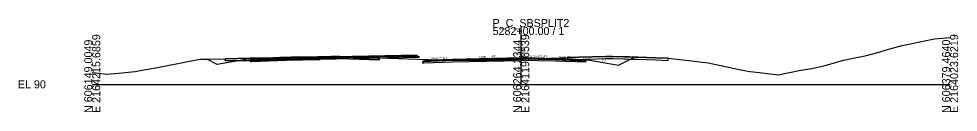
# Model space of a CAD drawing. Extents: x -26 to 1303, y -10 to 12033.
# Drawn here: x -25.7 to 302.8, y 1490.3 to 1522.8 of the extents above; entities that cross this region are included whole.
import ezdxf

# ---------------------------------------------------------------- set-up
doc = ezdxf.new("R2010")
doc.units = 0
for name, color, linetype in [('RD_GPK_XS_Cell', 7, 'Continuous'), ('RD_XS_Base', 7, 'Continuous'), ('RD_XS_ExGround', 7, 'Continuous'), ('RD_XS_ExPaveRet', 7, 'Continuous'), ('RD_XS_Greenside', 7, 'Continuous'), ('RD_XS_Pave', 7, 'Continuous'), ('RD_XS_PaveOvlay_CP', 7, 'Continuous'), ('RD_XS_TieSlope', 7, 'Continuous'), ('RD_XS_TX_Elev_EX', 7, 'Continuous'), ('RD_XS_TX_Elev_PR', 7, 'Continuous'), ('RD_XS_TX_ShdSlope', 7, 'Continuous'), ('RD_XS_TX_Slope', 7, 'Continuous')]:
    doc.layers.add(name, color=color, linetype=linetype)

msp = doc.modelspace()

# ---------------------------------------------------------------- linework, layer by layer
at = {"layer": 'RD_GPK_XS_Cell'}
for p, q in [((150, 1500), (150, 1520)), ((0, 1500), (150, 1500)), ((150, 1500), (300, 1500))]:
    msp.add_line(p, q, dxfattribs=at)
at = {"layer": 'RD_XS_Base'}
for p, q in [((55.67, 1508.47), (55.17, 1508.45)), ((55.17, 1508.45), (55.17, 1508.45)), ((55.17, 1508.45), (55.17, 1507.95)), ((55.17, 1507.95), (55.67, 1507.97)), ((67.67, 1508.95), (55.67, 1508.47)), ((55.67, 1508.47), (55.67, 1508.47)), ((55.67, 1507.97), (67.67, 1508.45)), ((55.67, 1507.97), (55.67, 1507.97)), ((79.67, 1509.19), (67.67, 1508.95)), ((67.67, 1508.95), (67.67, 1508.95)), ((67.67, 1508.45), (79.67, 1508.69)), ((67.67, 1508.45), (67.67, 1508.45)), ((79.67, 1509.19), (113.67, 1509.87)), ((114.17, 1509.38), (79.67, 1508.69)), ((79.67, 1508.69), (79.67, 1509.35)), ((79.67, 1509.35), (79.67, 1509.35)), ((79.67, 1509.35), (79.67, 1509.35)), ((79.67, 1509.35), (79.67, 1509.19)), ((79.67, 1509.19), (79.67, 1509.19)), ((79.67, 1508.69), (79.67, 1509.19)), ((79.67, 1509.19), (79.67, 1509.19)), ((79.67, 1509.19), (79.67, 1509.19)), ((79.67, 1508.69), (79.67, 1508.69)), ((103.67, 1509.67), (103.67, 1509.67)), ((103.67, 1509.67), (103.67, 1509.67)), ((103.67, 1509.17), (103.67, 1509.17)), ((103.67, 1509.17), (103.67, 1509.17)), ((113.67, 1509.87), (113.67, 1509.87)), ((114.17, 1509.88), (114.17, 1509.38)), ((114.17, 1509.85), (114.17, 1509.85)), ((116, 1507.99), (115.5, 1507.97)), ((115.5, 1507.97), (115.5, 1507.97)), ((115.5, 1507.97), (115.5, 1507.47)), ((126, 1508.39), (116, 1507.99)), ((116, 1507.99), (116, 1507.99)), ((150, 1508.87), (126, 1508.39)), ((126, 1508.39), (126, 1508.39)), ((126, 1507.89), (150, 1508.37)), ((150, 1508.37), (150, 1509.03)), ((150, 1509.03), (150, 1509.03)), ((150, 1509.03), (150, 1509.03)), ((150, 1509.03), (150, 1508.87)), ((150, 1508.87), (150, 1508.87)), ((150, 1508.87), (162, 1508.63)), ((150, 1508.87), (150, 1508.87)), ((150, 1508.37), (150, 1508.87)), ((150, 1508.87), (150, 1508.87)), ((150, 1508.87), (150, 1508.87)), ((162, 1508.13), (150, 1508.37)), ((150, 1508.37), (150, 1508.37)), ((150, 1508.37), (150, 1508.37)), ((162, 1508.63), (162, 1508.63)), ((162, 1508.63), (172, 1508.23)), ((172.5, 1507.71), (162, 1508.13)), ((162, 1508.13), (162, 1508.13)), ((172, 1508.23), (172, 1508.23)), ((172, 1508.23), (172.5, 1508.21)), ((172.5, 1508.21), (172.5, 1508.21)), ((172.5, 1508.21), (172.5, 1507.71)), ((115.5, 1507.47), (116, 1507.49)), ((116, 1507.49), (126, 1507.89)), ((116, 1507.49), (116, 1507.49)), ((126, 1507.89), (126, 1507.89))]:
    msp.add_line(p, q, dxfattribs=at)
at = {"layer": 'RD_XS_ExGround'}
msp.add_lwpolyline([(0, 1504.15), (1.09, 1504.03), (5.27, 1503.5), (9.12, 1503.91), (14.95, 1504.52), (17.41, 1504.97), (23.35, 1506.05), (32.24, 1507.71), (37.58, 1508.74), (41.11, 1508.77), (46.45, 1508.93), (55.21, 1509.08), (60.98, 1509.18), (65.65, 1509.33), (69.46, 1509.44), (73.23, 1509.5), (74.89, 1509.49), (78.87, 1509.64), (83.6, 1509.76), (84.11, 1509.77), (84.6, 1509.77), (86.33, 1509.74), (86.33, 1509.74), (86.43, 1509.73), (100.28, 1509.28), (117.22, 1508.69), (117.62, 1508.68), (117.8, 1508.67), (123.86, 1508.49), (124.05, 1508.49), (124.24, 1508.48), (132.52, 1508.33), (133.37, 1508.34), (134.4, 1508.32), (138.59, 1508.38), (143.59, 1508.54), (144.79, 1508.59), (145.31, 1508.62), (148.4, 1508.67), (156.03, 1508.97), (163.5, 1509.23), (166.22, 1509.32), (167.8, 1509.35), (170.12, 1509.44), (179.64, 1509.73), (180.8, 1509.75), (181.96, 1509.74), (186.03, 1509.62), (187.8, 1509.55), (189.98, 1509.5), (190.82, 1509.5), (197.1, 1509.27), (201.46, 1509.08), (208.65, 1508.31), (215.43, 1507.53), (219.8, 1506.53), (224.58, 1505.49), (226.86, 1505.02), (229.99, 1504.48), (233.4, 1504.1), (239.89, 1503.36), (247.75, 1504.89), (251.67, 1505.53), (253.79, 1506.05), (255.9, 1506.41), (262.02, 1508.21), (262.47, 1508.35), (262.84, 1508.43), (263.42, 1508.56), (267.77, 1509.5), (269.09, 1509.76), (270.78, 1510.11), (272.51, 1510.47), (274.23, 1510.99), (279.4, 1512.49), (282.76, 1513.46), (291.64, 1515.32), (294.49, 1515.88), (300, 1516.3)], dxfattribs=at)
at = {"layer": 'RD_XS_ExPaveRet'}
for points in [[(100.28, 1509.28), (100.28, 1509.28), (100.28, 1509.28), (100.28, 1508.53), (100.28, 1508.53), (86.43, 1508.98), (86.43, 1508.98), (86.33, 1508.99), (86.33, 1508.99), (86.33, 1508.99), (84.6, 1509.02), (84.6, 1509.02), (84.6, 1509.02), (84.6, 1509.02), (84.11, 1509.02), (83.6, 1509.01), (78.87, 1508.89), (78.87, 1508.89), (74.89, 1508.74), (74.89, 1508.74), (73.23, 1508.75), (73.23, 1508.75), (69.46, 1508.69), (69.46, 1508.69), (65.65, 1508.58), (65.65, 1508.58), (65.65, 1508.58), (60.98, 1508.43), (55.21, 1508.33), (55.21, 1508.33), (46.45, 1508.18), (46.45, 1508.18), (46.45, 1508.18), (46.45, 1508.93), (46.45, 1508.93), (46.45, 1508.93), (46.45, 1508.93), (55.21, 1509.08), (55.21, 1509.08), (60.98, 1509.18), (65.65, 1509.33), (65.65, 1509.33), (65.65, 1509.33), (69.46, 1509.44), (69.46, 1509.44), (73.23, 1509.5), (73.23, 1509.5), (74.89, 1509.49), (74.89, 1509.49), (78.87, 1509.64), (78.87, 1509.64), (83.6, 1509.76), (84.11, 1509.77), (84.6, 1509.77), (84.6, 1509.77), (84.6, 1509.77), (84.6, 1509.77), (86.33, 1509.74), (86.33, 1509.74), (86.33, 1509.74), (86.43, 1509.73), (86.43, 1509.73), (100.28, 1509.28)], [(86.43, 1509.73), (86.33, 1509.74), (86.33, 1509.74), (84.6, 1509.77), (84.11, 1509.77), (83.6, 1509.76), (78.87, 1509.64), (74.89, 1509.49), (73.23, 1509.5), (69.46, 1509.44), (65.65, 1509.33), (60.98, 1509.18), (55.21, 1509.08), (46.45, 1508.93), (46.45, 1508.93), (46.45, 1508.18), (46.45, 1508.18), (55.21, 1508.33), (60.98, 1508.43), (65.65, 1508.58), (69.46, 1508.69), (73.23, 1508.75), (74.89, 1508.74), (78.87, 1508.89), (83.6, 1509.01), (84.11, 1509.02), (84.6, 1509.02), (86.33, 1508.99), (86.33, 1508.99), (86.43, 1508.98), (100.28, 1508.53), (100.28, 1509.28), (86.43, 1509.73)], [(201.46, 1509.08), (197.1, 1509.27), (197.1, 1509.27), (190.82, 1509.5), (190.82, 1509.5), (189.98, 1509.5), (189.98, 1509.5), (187.8, 1509.55), (187.8, 1509.55), (186.03, 1509.62), (186.03, 1509.62), (181.96, 1509.74), (180.8, 1509.75), (180.8, 1509.75), (179.64, 1509.73), (179.64, 1509.73), (179.64, 1509.73), (170.12, 1509.44), (170.12, 1509.44), (167.8, 1509.35), (167.8, 1509.35), (166.22, 1509.32), (166.22, 1509.32), (166.22, 1509.32), (166.22, 1508.57), (166.22, 1508.57), (167.8, 1508.6), (167.8, 1508.6), (170.12, 1508.69), (170.12, 1508.69), (179.64, 1508.98), (179.64, 1508.98), (179.64, 1508.98), (180.8, 1509), (180.8, 1509), (181.96, 1508.99), (186.03, 1508.87), (186.03, 1508.87), (187.8, 1508.8), (187.8, 1508.8), (189.98, 1508.75), (189.98, 1508.75), (190.82, 1508.75), (190.82, 1508.75), (197.1, 1508.52), (197.1, 1508.52), (201.46, 1508.33), (201.46, 1508.33), (201.46, 1508.33), (201.46, 1509.08), (201.46, 1509.08), (201.46, 1509.08), (201.46, 1509.08)], [(201.46, 1509.08), (197.1, 1509.27), (190.82, 1509.5), (189.98, 1509.5), (187.8, 1509.55), (186.03, 1509.62), (181.96, 1509.74), (180.8, 1509.75), (179.64, 1509.73), (170.12, 1509.44), (167.8, 1509.35), (166.22, 1509.32), (166.22, 1509.32), (166.22, 1508.57), (166.22, 1508.57), (167.8, 1508.6), (170.12, 1508.69), (179.64, 1508.98), (180.8, 1509), (181.96, 1508.99), (186.03, 1508.87), (187.8, 1508.8), (189.98, 1508.75), (190.82, 1508.75), (197.1, 1508.52), (201.46, 1508.33), (201.46, 1509.08)]]:
    msp.add_lwpolyline(points, dxfattribs=at)
at = {"layer": 'RD_XS_Greenside'}
for p, q in [((43.67, 1506.97), (40.07, 1508.76)), ((53.67, 1508.63), (43.67, 1506.97)), ((174, 1508.39), (184, 1506.72)), ((184, 1506.72), (189.58, 1509.51))]:
    msp.add_line(p, q, dxfattribs=at)
at = {"layer": 'RD_XS_Pave'}
for p, q in [((67.67, 1509.27), (55.67, 1508.79)), ((55.67, 1508.63), (67.67, 1509.11)), ((67.67, 1509.11), (55.67, 1508.63)), ((55.67, 1508.47), (67.67, 1508.95)), ((55.67, 1508.79), (55.67, 1508.79)), ((55.67, 1508.79), (55.67, 1508.63)), ((55.67, 1508.63), (55.67, 1508.63)), ((55.67, 1508.63), (55.67, 1508.47)), ((79.67, 1509.51), (67.67, 1509.27)), ((67.67, 1509.11), (79.67, 1509.35)), ((79.67, 1509.35), (67.67, 1509.11)), ((67.67, 1509.27), (67.67, 1509.27)), ((67.67, 1508.95), (79.67, 1509.19)), ((67.67, 1509.11), (67.67, 1509.11)), ((67.67, 1509.11), (67.67, 1509.11)), ((67.67, 1508.95), (67.67, 1508.95)), ((113.67, 1510.19), (79.67, 1509.51)), ((113.67, 1510.03), (79.67, 1509.35)), ((79.67, 1509.35), (113.67, 1510.03)), ((79.67, 1509.19), (114.17, 1509.88)), ((79.67, 1509.51), (79.67, 1509.51)), ((79.67, 1509.19), (79.67, 1509.35)), ((79.67, 1509.35), (79.67, 1509.35)), ((79.67, 1509.35), (79.67, 1509.35)), ((79.67, 1509.35), (79.67, 1509.35)), ((79.67, 1509.35), (79.67, 1509.35)), ((79.67, 1509.35), (79.67, 1509.19)), ((79.67, 1509.35), (79.67, 1509.35)), ((79.67, 1509.19), (79.67, 1509.19)), ((79.67, 1509.19), (79.67, 1509.19)), ((103.67, 1509.99), (103.67, 1509.99)), ((103.67, 1509.99), (103.67, 1509.99)), ((103.67, 1509.83), (103.67, 1509.83)), ((103.67, 1509.83), (103.67, 1509.83)), ((103.67, 1509.83), (103.67, 1509.83)), ((103.67, 1509.83), (103.67, 1509.83)), ((103.67, 1509.67), (103.67, 1509.67)), ((103.67, 1509.67), (103.67, 1509.67)), ((113.67, 1510.03), (113.67, 1510.19)), ((113.67, 1510.19), (113.67, 1510.19)), ((113.67, 1509.87), (113.67, 1510.03)), ((113.67, 1510.03), (113.67, 1510.03)), ((126, 1508.71), (116, 1508.31)), ((126, 1508.55), (116, 1508.15)), ((116, 1508.15), (126, 1508.55)), ((116, 1507.99), (126, 1508.39)), ((116, 1508.31), (116, 1508.31)), ((116, 1508.31), (116, 1508.15)), ((116, 1508.15), (116, 1508.15)), ((116, 1508.15), (116, 1507.99)), ((150, 1509.19), (126, 1508.71)), ((150, 1509.03), (126, 1508.55)), ((126, 1508.55), (150, 1509.03)), ((126, 1508.39), (150, 1508.87)), ((126, 1508.71), (126, 1508.71)), ((126, 1508.55), (126, 1508.55)), ((126, 1508.55), (126, 1508.55)), ((126, 1508.39), (126, 1508.39)), ((162, 1508.95), (150, 1509.19)), ((150, 1509.19), (150, 1509.19)), ((150, 1509.19), (150, 1509.19)), ((150, 1508.87), (150, 1509.03)), ((150, 1509.03), (150, 1509.03)), ((150, 1509.03), (150, 1509.03)), ((162, 1508.79), (150, 1509.03)), ((150, 1509.03), (150, 1509.03)), ((150, 1509.03), (150, 1509.03)), ((150, 1509.03), (150, 1509.03)), ((150, 1509.03), (150, 1508.87)), ((150, 1509.03), (150, 1509.03)), ((150, 1509.03), (150, 1509.03)), ((150, 1509.03), (162, 1508.79)), ((150, 1508.87), (150, 1508.87)), ((150, 1508.87), (150, 1508.87)), ((150, 1508.87), (150, 1508.87)), ((150, 1508.87), (162, 1508.63)), ((172, 1508.55), (162, 1508.95)), ((162, 1508.95), (162, 1508.95)), ((172, 1508.39), (162, 1508.79)), ((162, 1508.79), (162, 1508.79)), ((162, 1508.79), (162, 1508.79)), ((162, 1508.79), (172, 1508.39)), ((162, 1508.63), (172, 1508.23)), ((162, 1508.63), (162, 1508.63)), ((172, 1508.39), (172, 1508.55)), ((172, 1508.55), (172, 1508.55)), ((172, 1508.23), (172, 1508.39)), ((172, 1508.39), (172, 1508.39))]:
    msp.add_line(p, q, dxfattribs=at)
at = {"layer": 'RD_XS_PaveOvlay_CP'}
for p, q in [((67.67, 1509.27), (55.67, 1508.79)), ((79.67, 1509.51), (67.67, 1509.27)), ((67.67, 1509.27), (67.67, 1509.27)), ((113.67, 1510.19), (79.67, 1509.51)), ((79.67, 1509.51), (79.67, 1509.51)), ((103.67, 1509.99), (103.67, 1509.99)), ((103.67, 1509.99), (103.67, 1509.99)), ((126, 1508.71), (116, 1508.31)), ((150, 1509.19), (126, 1508.71)), ((126, 1508.71), (126, 1508.71)), ((162, 1508.95), (150, 1509.19)), ((150, 1509.19), (150, 1509.19)), ((150, 1509.19), (150, 1509.19)), ((172, 1508.55), (162, 1508.95)), ((162, 1508.95), (162, 1508.95))]:
    msp.add_line(p, q, dxfattribs=at)
at = {"layer": 'RD_XS_TieSlope'}
for p, q in [((55.67, 1508.79), (53.67, 1508.63)), ((172, 1508.55), (174, 1508.39))]:
    msp.add_line(p, q, dxfattribs=at)

# ---------------------------------------------------------------- texts
at = {"layer": 'RD_GPK_XS_Cell'}
for s, p in [('P_C_SBSPLIT2', (140, 1520)), ('5282+00.00 / 1', (140, 1517.2)), ('EL 90', (-26, 1498.6))]:
    msp.add_text(s, height=2.8, dxfattribs=at).set_placement(p)
for s, p in [('N 606149.0049', (0, 1490)), ('E 2164215.6859', (2.8, 1490)), ('N 606264.2344', (150, 1490)), ('E 2164119.6539', (152.8, 1490)), ('N 606379.4640', (300, 1490)), ('E 2164023.6219', (302.8, 1490))]:
    msp.add_text(s, height=2.8, rotation=90, dxfattribs=at).set_placement(p)
at = {"layer": 'RD_XS_TX_Elev_EX'}
msp.add_text('98.73', height=0.6, rotation=90, dxfattribs=at).set_placement((149.71, 1510.16))
at = {"layer": 'RD_XS_TX_Elev_PR'}
msp.add_text('99.19', height=1, rotation=90, dxfattribs=at).set_placement((151.32, 1509.7))
at = {"layer": 'RD_XS_TX_ShdSlope'}
msp.add_text('12.5:1', height=0.75, rotation=355.4261, dxfattribs=at).set_placement((171.56, 1508.89))
at = {"layer": 'RD_XS_TX_Slope'}
for s, rotation, p in [('0.040 FT./FT.', 2.2906, (118.15, 1508.61)), ('0.020 FT./FT.', 1.1458, (135.16, 1509.11)), ('0.020 FT./FT.', 358.8542, (153.16, 1509.34)), ('0.040 FT./FT.', 357.7094, (163.17, 1509.12)), ('6:1', 350.5358, (178.13, 1508.1)), ('2:1', 26.5651, (185.77, 1508.04))]:
    msp.add_text(s, height=0.75, rotation=rotation, dxfattribs=at).set_placement(p)

doc.saveas('drawing.dxf')
